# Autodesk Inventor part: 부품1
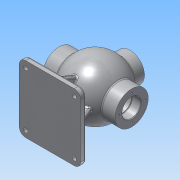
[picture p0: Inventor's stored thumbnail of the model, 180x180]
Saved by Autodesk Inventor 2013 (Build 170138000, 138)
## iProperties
Created: 2018-06
Part Number: 부품1
Material: 알루미늄 6061
Document SubType Name: Modeling
Designer: Administrator
Density: 2.71 g/cm^3
Mass: 1509.6 g
Surface Area: 1153.7 cm^2
Volume: 557.047 cm^3
Author: Administrator
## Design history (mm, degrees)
sketch "스케치1"
  geometry: L1 (0, 53)-(0, -53); A1 r 53 centre (0, 0) between (0, -53) and (0, 53); 2 further points
  constraints: 2 coincident, 2 end point, 2 point on circle, 1 centre point, 1 midpoint, 1 vertical
  dimensions: "d1" = 106 diameter of A1
revolve "회전1" sketch "스케치1" stored, may be unused: angle "d2" = 90 deg
node "작업 평면1"
sketch "스케치2"
  geometry: C1 r 31 at (0, 0); 1 further point
  constraints: 1 centre point, 1 coincident
  dimensions: "d4" = 62 diameter of C1
extrude "돌출1" join sketch "스케치2" stored distance "d5" = 10; taper "d6" = 0 deg
sketch "스케치4"
  geometry: C1 r 31 at (0, 0) reference; C2 r 17.5 at (0, 0)
  constraints: 1 centre point, 1 coincident
  dimensions: "d7" = 35 diameter of C2
extrude "돌출2" cut sketch "스케치4" distance "d9" = 16; taper "d10" = 0 deg
sketch "스케치5"
  geometry: C1 r 17.5 at (0, 0) reference; C2 r 18.5 at (0, 0)
  constraints: 1 centre point, 1 coincident
  dimensions: "d12" = 37 diameter of C2
extrude "돌출3" cut sketch "스케치5" distance "d13" = 1.75; taper "d14" = 0 deg
node "작업 평면2"
sketch "스케치6"
  geometry: C1 r 31 at (0, 0); 1 further point
  constraints: 1 centre point, 1 coincident
  dimensions: "d16" = 62 diameter of C1
extrude "돌출4" join sketch "스케치6" stored distance "d17" = 62 (= d16); taper "d18" = 0 deg
sketch "스케치7"
  geometry: C1 r 31 at (0, 0) reference; C2 r 17.5 at (0, 0)
  constraints: 1 centre point, 1 coincident
  dimensions: "d19" = 35 diameter of C2
extrude "돌출5" cut sketch "스케치7" stored distance "d20" = 1.75; taper "d21" = 0 deg
node "작업 평면3"
sketch "스케치8"
  geometry: C1 r 27 at (0, 0); 1 further point
  constraints: 1 centre point, 1 coincident
  dimensions: "d23" = 54 diameter of C1
extrude "돌출6" join sketch "스케치8" stored distance "d24" = 1.75; taper "d25" = 0 deg
sketch "스케치9"
  geometry: C1 r 27 at (0, 0) reference; C2 r 13 at (0, 0)
  constraints: 1 centre point, 1 coincident
  dimensions: "d26" = 26 diameter of C2
sketch "스케치10"
  geometry: L1 (0, 43)-(0, -43); A1 r 43 centre (0, 0) between (0, -43) and (0, 43); 1 further point
  constraints: 2 end point, 2 point on circle, 1 centre point, 1 coincident, 1 midpoint, 1 vertical
  dimensions: "d27" = 86 diameter of A1
revolve "회전2" sketch "스케치10" stored, may be unused: angle "d28" = 90 deg
extrude "돌출7" cut sketch "스케치9" stored distance "d29" = 1.75; taper "d30" = 0 deg
node "작업 평면4"
sketch "스케치13"
  geometry: L1 (-57.5, 62.5)-(57.5, 62.5); L2 (57.5, 62.5)-(57.5, -62.5); L3 (57.5, -62.5)-(-57.5, -62.5); L4 (-57.5, -62.5)-(-57.5, 62.5); L5 (-57.5, 62.5)-(57.5, -62.5); L6 (57.5, 62.5)-(-57.5, -62.5); 1 further point
  constraints: 12 end point, 2 midpoint, 2 parallel, 1 horizontal, 1 perpendicular
  dimensions: "d36" = 115 distance of L2.end L3.end; "d37" = 125 distance of L1.end L2.end
extrude "돌출9" join sketch "스케치13" distance "d38" = 10; taper "d39" = 0 deg
sketch "스케치17"
  geometry: L1 (47.5, -4)-(-47.5, -4); L2 (-47.5, -4)-(-47.5, 4); L3 (-47.5, 4)-(47.5, 4); L4 (47.5, 4)-(47.5, -4); L5 (47.5, -4)-(-47.5, 4); L6 (-47.5, -4)-(47.5, 4); 1 further point
  constraints: 12 end point, 2 midpoint, 2 parallel, 1 horizontal, 1 perpendicular
  dimensions: "d46" = 95 distance of L2.end L3.end; "d47" = 8 distance of L1.end L2.end
extrude "돌출10" join sketch "스케치17" stored distance "d48" = 10; taper "d49" = 0 deg
sketch "스케치18"
  geometry: L1 (-75, 52.5)-(-43.9, 39.935); L2 (-85, 62.5)-(-75, 62.5) reference; L3 (-75, -62.5)-(-75, 62.5) reference; 1 further point
  constraints: 2 end point, 1 point on line
  dimensions: "d50" = 10 distance from line of L2 L1.start; "d51" = 22 deg angle of L1 L2
feature "리브1" sketch "스케치18" dims "d52" = 1, "d53" = 8, "d54" = 0, "d55" = 0, "d56" = 1, "d57" = 1
feature "면 기울기1" dims angle "d58" = 22 deg
fillet "모깎기1" dims "d59" = 12
sketch "스케치21"
  geometry: A1 r 12 centre (-45.5, 50.5) between (-45.5, 62.5) and (-57.5, 50.5) reference; 2 further points
  constraints: 1 coincident
hole "구멍1" sketch "스케치21" at (-45.5, 50.5) diameter "d60" = 8; stored, may be unused: countersink angle "d64" = 90 deg, drill point angle "d66" = 118 deg; dims "d61" = 6, "d62" = 12, "d63" = 3, "d65" = 8
fillet "모깎기2" dims "d67" = 3
fillet "모깎기3" dims "d68" = 3
fillet "모깎기4" dims "d69" = 3
fillet "모깎기5" dims "d70" = 3
chamfer "모따기1" distance "d71" = 1; stored, may be unused: second distance "d72" = 2, angle "d73" = 45 deg
node "작업 평면5"
sketch "스케치22"
  geometry: C1 r 18.5 at (0, 0); 1 further point
  constraints: 1 centre point, 1 coincident
  dimensions: "d75" = 37 diameter of C1
extrude "돌출11" cut sketch "스케치22" distance "d76" = 1.75; taper "d77" = 0 deg
sketch "스케치23"
  geometry: C1 r 27 at (0, 0) reference; 1 further point
  constraints: 1 vertical alignment
  dimensions: "d78" = 20 distance of C1.centre point (0, 20)
hole "구멍2" sketch "스케치23" at (0, 20) diameter "d79" = 3.242; stored, may be unused: countersink angle "d83" = 90 deg, drill point angle "d85" = 118 deg; dims "d80" = 9, "d81" = 4, "d82" = 2, "d84" = 11
sketch "스케치24"
  geometry: C1 r 31 at (0, 0) reference; 1 further point
  constraints: 1 vertical alignment
  dimensions: "d89" = 24 distance of C1.centre point (0, 24)
hole "구멍3" sketch "스케치24" at (0, 24) diameter "d90" = 3.242; stored, may be unused: countersink angle "d94" = 90 deg, drill point angle "d96" = 118 deg; dims "d91" = 16, "d92" = 4, "d93" = 2, "d95" = 19
sketch "스케치25"
  geometry: C1 r 31 at (0, 0) reference; 1 further point
  constraints: 1 vertical alignment
  dimensions: "d100" = 22.5 distance of C1.centre point (0, 22.5)
hole "구멍4" sketch "스케치25" at (0, 22.5) diameter "d101" = 3.242; stored, may be unused: countersink angle "d105" = 90 deg, drill point angle "d107" = 118 deg; dims "d102" = 12, "d103" = 4, "d104" = 2, "d106" = 15
node "작업 평면6"
sketch "스케치26"
  geometry: L1 (-27, 65)-(27, 65) reference; L2 (-27, 47.286)-(27, 47.286) reference; L3 (-27, 65)-(-27, 47.286) reference; 2 further points
  constraints: 1 other
  dimensions: "d112" = 27 distance from line of L3 point (0, 55); "d113" = 10 distance from line of L1 point (0, 55)
feature "엠보싱1" sketch "스케치26" dims "d114" = 0.5, "d115" = 0
node "솔리드1"
mirror "대칭1"
mirror "대칭2"
mirror "대칭3"
pattern_circular "원형 패턴1" dims angle "d87" = 360 deg
pattern_circular "원형 패턴2" dims angle "d98" = 360 deg
pattern_circular "원형 패턴3" dims angle "d109" = 360 deg
node "투영된 루프2"
other parameters: "d3" = 68, "d15" = -68, "d22" = 65, "d74" = -16, "d111" = -27
